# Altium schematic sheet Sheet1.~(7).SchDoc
size A4; SheetNumber: 1; SheetTotal: 1
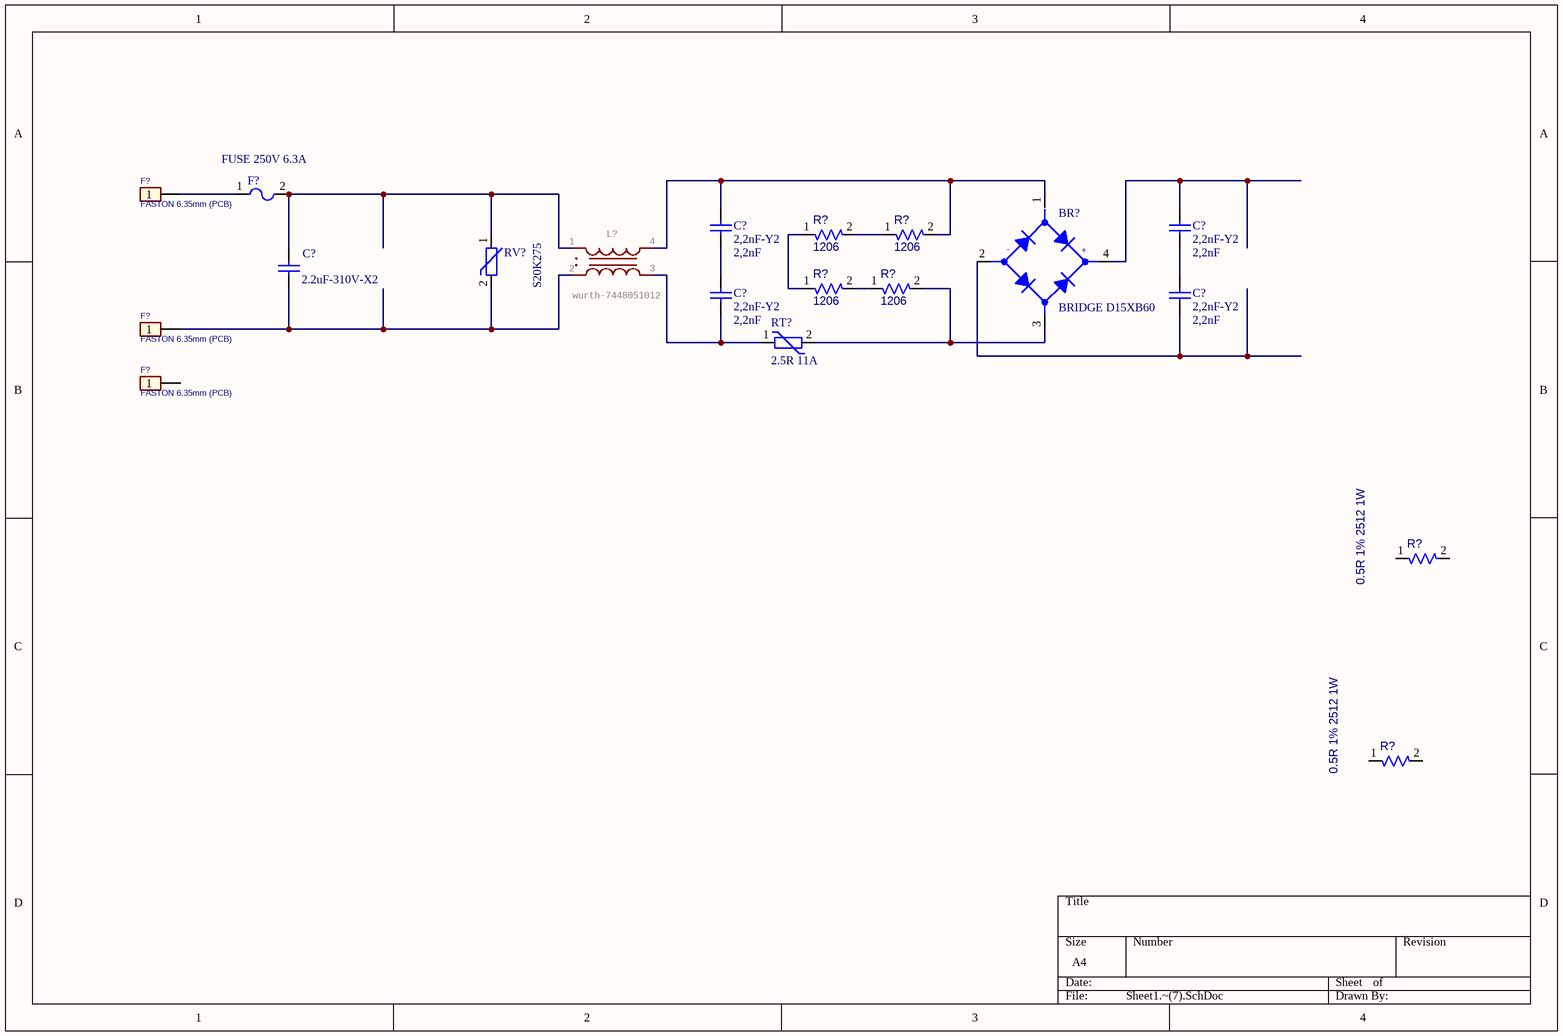
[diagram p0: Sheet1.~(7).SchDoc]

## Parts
(Parts that share a designator on the sheet are numbered #1, #2 ... from top to bottom, then left to right.)
BR?  BRIDGE D15XB60
C?#1  2,2nF-Y2  value 2,2nF
C?#2  2,2nF-Y2  value 2,2nF
C?#3  2.2uF-310V-X2
C?#4  2,2nF-Y2  value 2,2nF
C?#5  2,2nF-Y2  value 2,2nF
F?#1  FASTON 6.35mm (PCB)  [FASTON_M_PCB_6.35x0.81]
F?#2  FUSE 250V 6.3A  [BEL_FUSE_0697A6300-01]
F?#3  FASTON 6.35mm (PCB)  [FASTON_M_PCB_6.35x0.81]
F?#4  FASTON 6.35mm (PCB)  [FASTON_M_PCB_6.35x0.81]
L?  wurth-7448051012  [WE-CMBNC_XL_7448051012]
R?#1  1206  [1206_UP_RES]
R?#2  1206  [1206_UP_RES]
R?#3  1206  [1206_UP_RES]
R?#4  1206  [1206_UP_RES]
R?#5  0.5R 1% 2512 1W  [2512_up]
R?#6  0.5R 1% 2512 1W  [2512_up]
RT?  2.5R 11A
RV?  S20K275

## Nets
NetBR?_1: BR?.1(AC1) C?#1.2 L?.4 R?#2.2
NetBR?_2: BR?.2(-DC) C?#5.1
NetBR?_3: BR?.3(AC2) R?#4.2 RT?.2
NetBR?_4: BR?.4(+DC) C?#2.2
NetC?#1_1: C?#1.1 C?#4.2
NetC?#2_1: C?#2.1 C?#5.2
NetC?#3_1: C?#3.1 F?#2.2 L?.1 RV?.1
NetC?#3_2: C?#3.2 F?#3.1 L?.2 RV?.2
NetC?#4_1: C?#4.1 L?.3 RT?.1
NetF?#1_1: F?#1.1 F?#2.1
NetR?#1_1: R?#1.1 R?#3.1
NetR?#1_2: R?#1.2 R?#2.1
NetR?#3_2: R?#3.2 R?#4.1

Not connected (* = marked no-connect by the designer): F?#4 1; R?#5 1 2; R?#6 1 2

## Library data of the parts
BR? = BRIDGE_D15XB60_15A_600V: BRIDGE D15XB60 15A 600V; Costo: 0; Aggiornato: NO
C?#1 C?#2 C?#4 C?#5 = Cap: 2,2nF-Y2-300V MURATA DE6E3KJ222MA4B
C?#3 = Cap: 2.2uF-310V-X2  VISHAY F339M/52231MIM2T0
F?#1 F?#3 F?#4 = FASTON_M_PCB_6.35mm: FASTON M PCB 6.35mm; Hpcode: FASTMASCSTAMP; Costo: 0,01; Aggiornato: s; ContoLavoro: 0
F?#2 = FUSE_250V_6.3A_T_BEL_FUSE_0697A6300-01: FUSE 250Vac 6.3A Time Delay BEL FUSE 0697A6300-01; Costo: 0,26; Aggiornato: S; ContoLavoro: 0
L? = WE-CMBNC_XL_7448051012: GateName_1: G$1; IR: 10A; RDC: 15mOhm; VR: 250  V (AC); VT: 1500  V (AC)
R?#1-R?#4 = R_0.33_1%_1206: 1206 SMD RESISTOR; Aggiornato: s; ContoLavoro: 0
R?#5 R?#6 = R_0.5R_1%_2512: 0.5R 1% 2512 1W SMD RESISTOR; Costo: 0,40; Value: 0.5; Aggiornato: s; ContoLavoro: 0
RT? = RT_2.5R_10A: NTC 2.5R 11A  TDK B57364S0259M0 21x7; Costo: 0; Aggiornato: NO
RV? = VARISTOR: VARISTORE TDK S20K275 B72220S0271K101; Aggiornato: NO; ContoLavoro: 0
